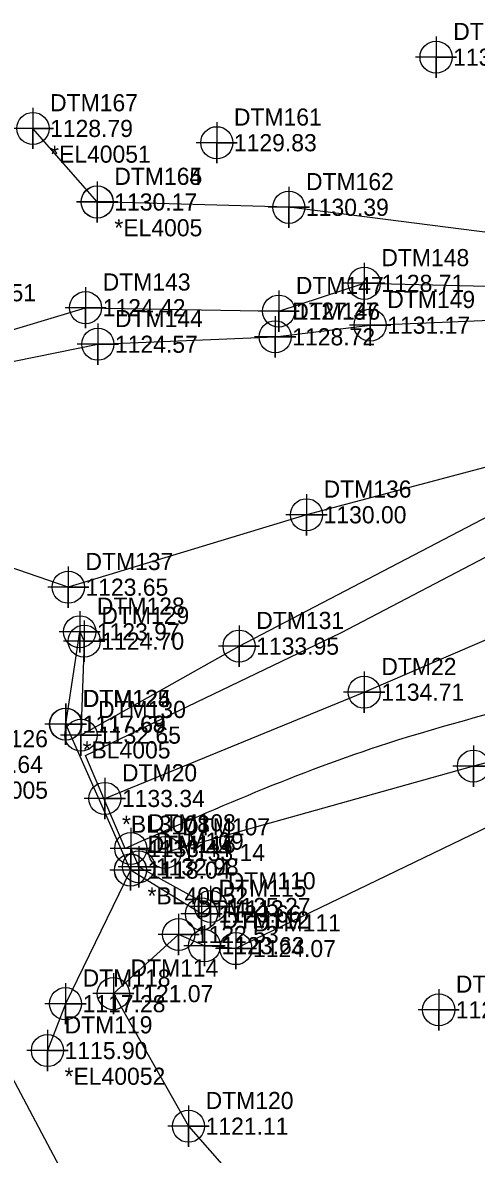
# Model space of a CAD drawing. Extents: x 1286409 to 1286829, y 857931 to 858308.
# Drawn here: x 1286649.1 to 1286715.3, y 858130 to 858295.1 of the extents above; entities that cross this region are included whole.
import ezdxf

# ---------------------------------------------------------------- set-up
doc = ezdxf.new("R2010")
doc.units = 0
for name, color, linetype in [('Exist DTM Breakline', 7, 'Continuous'), ('Exist DTM Breakline Cogo Comment', 7, 'Continuous'), ('Exist DTM Breakline Cogo Elevation', 7, 'Continuous'), ('Exist DTM Breakline Cogo Number', 7, 'Continuous'), ('Exist DTM Breakline Cogo Point CELL', 7, 'Continuous'), ('Exist DTM Crownline', 7, 'Continuous'), ('Exist DTM Crownline Cogo Comment', 7, 'Continuous'), ('Exist DTM Crownline Cogo Elevation', 7, 'Continuous'), ('Exist DTM Crownline Cogo Number', 7, 'Continuous'), ('Exist DTM Crownline Cogo Point CELL', 7, 'Continuous'), ('Exist DTM Regular Point CELL', 7, 'Continuous'), ('Exist DTM Regular Point Cogo Elevation', 7, 'Continuous'), ('Exist DTM Regular Point Cogo Number', 7, 'Continuous'), ('Exist Hydro Stream or Body of Water', 7, 'Continuous'), ('Exist Roads EOP', 7, 'Continuous')]:
    doc.layers.add(name, color=color, linetype=linetype)

msp = doc.modelspace()

# ---------------------------------------------------------------- linework, layer by layer
at = {"layer": 'Exist DTM Breakline'}
for points in [[(1286632.493, 858242.571), (1286660.074, 858248.148), (1286685.945, 858249.23), (1286699.802, 858250.923), (1286734.824, 858252.386), (1286736.062, 858257.139), (1286731.751, 858264.514), (1286727.165, 858263.134), (1286687.944, 858268.125), (1286659.976, 858268.899), (1286650.61, 858279.628)], [(1286616.952, 858240.566), (1286629.155, 858244.707), (1286658.287, 858253.478), (1286686.461, 858252.975), (1286698.943, 858257.032), (1286730.846, 858256.269)], [(1286748.85, 858195.515), (1286714.87, 858186.6), (1286669.883, 858173.996), (1286664.879, 858174.577), (1286666.033, 858171.901), (1286676.529, 858166.124), (1286675.191, 858165.032), (1286664.853, 858171.436), (1286655.406, 858192.72), (1286657.428, 858206.193), (1286658.087, 858204.832), (1286657.611, 858191.117), (1286680.683, 858204.103), (1286719.44, 858224.327), (1286731.354, 858234.119), (1286690.517, 858223.266), (1286655.768, 858212.7), (1286632.397, 858220.726)], [(1286787.57, 858150.977), (1286775.181, 858174.894), (1286765.217, 858193.137), (1286755.797, 858193.361), (1286718.64, 858178.527), (1286680.221, 858159.977), (1286675.641, 858160.401), (1286671.867, 858162.031), (1286662.339, 858153.405), (1286673.303, 858134.067), (1286682.298, 858123.811), (1286697.007, 858100.077), (1286709.742, 858055.54)], [(1286664.828, 858171.428), (1286655.358, 858151.939), (1286652.726, 858145.104)]]:
    msp.add_lwpolyline(points, dxfattribs=at)
at = {"layer": 'Exist DTM Breakline Cogo Point CELL'}
for points in [[(1286650.61, 858282.628), (1286650.61, 858276.628), (1286650.61, 858279.628), (1286653.61, 858279.628), (1286647.61, 858279.628)], [(1286659.976, 858271.899), (1286659.976, 858265.899), (1286659.976, 858268.899), (1286662.976, 858268.899), (1286656.976, 858268.899)], [(1286659.988, 858271.89), (1286659.988, 858265.89), (1286659.988, 858268.89), (1286662.988, 858268.89), (1286656.988, 858268.89)], [(1286687.944, 858271.125), (1286687.944, 858265.125), (1286687.944, 858268.125), (1286690.944, 858268.125), (1286684.944, 858268.125)], [(1286698.943, 858260.032), (1286698.943, 858254.032), (1286698.943, 858257.032), (1286701.943, 858257.032), (1286695.943, 858257.032)], [(1286658.287, 858256.478), (1286658.287, 858250.478), (1286658.287, 858253.478), (1286661.287, 858253.478), (1286655.287, 858253.478)], [(1286686.461, 858255.975), (1286686.461, 858249.975), (1286686.461, 858252.975), (1286689.461, 858252.975), (1286683.461, 858252.975)], [(1286699.802, 858253.923), (1286699.802, 858247.923), (1286699.802, 858250.923), (1286702.802, 858250.923), (1286696.802, 858250.923)], [(1286685.945, 858252.23), (1286685.945, 858246.23), (1286685.945, 858249.23), (1286688.945, 858249.23), (1286682.945, 858249.23)], [(1286660.074, 858251.148), (1286660.074, 858245.148), (1286660.074, 858248.148), (1286663.074, 858248.148), (1286657.074, 858248.148)], [(1286690.517, 858226.266), (1286690.517, 858220.266), (1286690.517, 858223.266), (1286693.517, 858223.266), (1286687.517, 858223.266)], [(1286655.768, 858215.7), (1286655.768, 858209.7), (1286655.768, 858212.7), (1286658.768, 858212.7), (1286652.768, 858212.7)], [(1286657.428, 858209.193), (1286657.428, 858203.193), (1286657.428, 858206.193), (1286660.428, 858206.193), (1286654.428, 858206.193)], [(1286658.087, 858207.832), (1286658.087, 858201.832), (1286658.087, 858204.832), (1286661.087, 858204.832), (1286655.087, 858204.832)], [(1286680.683, 858207.103), (1286680.683, 858201.103), (1286680.683, 858204.103), (1286683.683, 858204.103), (1286677.683, 858204.103)], [(1286655.354, 858195.717), (1286655.354, 858189.717), (1286655.354, 858192.717), (1286658.354, 858192.717), (1286652.354, 858192.717)], [(1286655.406, 858195.72), (1286655.406, 858189.72), (1286655.406, 858192.72), (1286658.406, 858192.72), (1286652.406, 858192.72)], [(1286657.611, 858194.117), (1286657.611, 858188.117), (1286657.611, 858191.117), (1286660.611, 858191.117), (1286654.611, 858191.117)], [(1286714.87, 858189.6), (1286714.87, 858183.6), (1286714.87, 858186.6), (1286717.87, 858186.6), (1286711.87, 858186.6)], [(1286664.879, 858177.577), (1286664.879, 858171.577), (1286664.879, 858174.577), (1286667.879, 858174.577), (1286661.879, 858174.577)], [(1286669.883, 858176.996), (1286669.883, 858170.996), (1286669.883, 858173.996), (1286672.883, 858173.996), (1286666.883, 858173.996)], [(1286664.828, 858174.428), (1286664.828, 858168.428), (1286664.828, 858171.428), (1286667.828, 858171.428), (1286661.828, 858171.428)], [(1286664.853, 858174.436), (1286664.853, 858168.436), (1286664.853, 858171.436), (1286667.853, 858171.436), (1286661.853, 858171.436)], [(1286666.033, 858174.901), (1286666.033, 858168.901), (1286666.033, 858171.901), (1286669.033, 858171.901), (1286663.033, 858171.901)], [(1286675.191, 858168.032), (1286675.191, 858162.032), (1286675.191, 858165.032), (1286678.191, 858165.032), (1286672.191, 858165.032)], [(1286676.529, 858169.124), (1286676.529, 858163.124), (1286676.529, 858166.124), (1286679.529, 858166.124), (1286673.529, 858166.124)], [(1286671.867, 858165.031), (1286671.867, 858159.031), (1286671.867, 858162.031), (1286674.867, 858162.031), (1286668.867, 858162.031)], [(1286675.641, 858163.401), (1286675.641, 858157.401), (1286675.641, 858160.401), (1286678.641, 858160.401), (1286672.641, 858160.401)], [(1286680.221, 858162.977), (1286680.221, 858156.977), (1286680.221, 858159.977), (1286683.221, 858159.977), (1286677.221, 858159.977)], [(1286662.339, 858156.405), (1286662.339, 858150.405), (1286662.339, 858153.405), (1286665.339, 858153.405), (1286659.339, 858153.405)], [(1286655.358, 858154.939), (1286655.358, 858148.939), (1286655.358, 858151.939), (1286658.358, 858151.939), (1286652.358, 858151.939)], [(1286652.726, 858148.104), (1286652.726, 858142.104), (1286652.726, 858145.104), (1286655.726, 858145.104), (1286649.726, 858145.104)], [(1286673.303, 858137.067), (1286673.303, 858131.067), (1286673.303, 858134.067), (1286676.303, 858134.067), (1286670.303, 858134.067)]]:
    msp.add_lwpolyline(points, dxfattribs=at)
for centre in [(1286650.61, 858279.628), (1286659.976, 858268.899), (1286659.988, 858268.89), (1286687.944, 858268.125), (1286698.943, 858257.032), (1286658.287, 858253.478), (1286686.461, 858252.975), (1286699.802, 858250.923), (1286660.074, 858248.148), (1286685.945, 858249.23), (1286690.517, 858223.266), (1286655.768, 858212.7), (1286657.428, 858206.193), (1286658.087, 858204.832), (1286680.683, 858204.103), (1286655.354, 858192.717), (1286655.406, 858192.72), (1286657.611, 858191.117), (1286714.87, 858186.6), (1286664.879, 858174.577), (1286669.883, 858173.996), (1286666.033, 858171.901), (1286664.828, 858171.428), (1286664.853, 858171.436), (1286676.529, 858166.124), (1286675.191, 858165.032), (1286671.867, 858162.031), (1286675.641, 858160.401), (1286680.221, 858159.977), (1286662.339, 858153.405), (1286655.358, 858151.939), (1286652.726, 858145.104), (1286673.303, 858134.067)]:
    msp.add_circle(centre, 2.344, dxfattribs=at)
at = {"layer": 'Exist DTM Crownline'}
msp.add_lwpolyline([(1286661.096, 858181.88), (1286698.94, 858197.382), (1286724.907, 858208.588), (1286744.568, 858217.621), (1286760.393, 858225.322)], dxfattribs=at)
at = {"layer": 'Exist DTM Crownline Cogo Point CELL'}
for points in [[(1286698.94, 858200.382), (1286698.94, 858194.382), (1286698.94, 858197.382), (1286701.94, 858197.382), (1286695.94, 858197.382)], [(1286661.096, 858184.88), (1286661.096, 858178.88), (1286661.096, 858181.88), (1286664.096, 858181.88), (1286658.096, 858181.88)]]:
    msp.add_lwpolyline(points, dxfattribs=at)
for centre in [(1286698.94, 858197.382), (1286661.096, 858181.88)]:
    msp.add_circle(centre, 2.344, dxfattribs=at)
at = {"layer": 'Exist DTM Regular Point CELL'}
for points in [[(1286709.422, 858293.025), (1286709.422, 858287.025), (1286709.422, 858290.025), (1286712.422, 858290.025), (1286706.422, 858290.025)], [(1286677.425, 858280.541), (1286677.425, 858274.541), (1286677.425, 858277.541), (1286680.425, 858277.541), (1286674.425, 858277.541)], [(1286709.806, 858154.046), (1286709.806, 858148.046), (1286709.806, 858151.046), (1286712.806, 858151.046), (1286706.806, 858151.046)]]:
    msp.add_lwpolyline(points, dxfattribs=at)
for centre in [(1286709.422, 858290.025), (1286677.425, 858277.541), (1286709.806, 858151.046)]:
    msp.add_circle(centre, 2.344, dxfattribs=at)
at = {"layer": 'Exist Hydro Stream or Body of Water'}
msp.add_lwpolyline([(1286685.865, 858065.012), (1286665.776, 858106.892), (1286641.007, 858153.512), (1286624.223, 858201.931), (1286608.049, 858245.959), (1286588.044, 858292.077)], dxfattribs=at)
at = {"layer": 'Exist Roads EOP'}
for points in [[(1286658.291, 858188.167), (1286695.619, 858206.081), (1286719.784, 858218.735)], [(1286664.079, 858174.593), (1286658.291, 858188.167)]]:
    msp.add_lwpolyline(points, dxfattribs=at)
msp.add_spline([(1286787.169, 858167.69), (1286776.787, 858189.619), (1286767.655, 858197.136), (1286752.603, 858202.097), (1286728.107, 858197.379), (1286702.359, 858189.909), (1286664.079, 858174.593)], degree=3, dxfattribs=at)

# ---------------------------------------------------------------- texts
at = {"layer": 'Exist DTM Breakline Cogo Comment'}
for s, p in [('*EL40051', (1286653.11, 858274.628)), ('*EL4005', (1286662.488, 858263.89)), ('*EL40051', (1286636.373, 858254.409)), ('*BL4005', (1286657.854, 858187.717)), ('*BL4005', (1286639.973, 858181.849)), ('*BL40052', (1286667.328, 858166.428)), ('*EL40052', (1286655.226, 858140.104))]:
    msp.add_text(s, height=2.5, dxfattribs=at).set_placement(p)
at = {"layer": 'Exist DTM Breakline Cogo Elevation'}
for s, p in [('1128.79', (1286653.11, 858278.378)), ('1130.17', (1286662.476, 858267.649)), ('1130.17', (1286662.488, 858267.64)), ('1130.39', (1286690.444, 858266.875)), ('1128.71', (1286701.443, 858255.782)), ('1124.42', (1286660.787, 858252.228)), ('1127.37', (1286688.961, 858251.725)), ('1131.17', (1286702.302, 858249.673)), ('1128.72', (1286688.445, 858247.98)), ('1124.57', (1286662.574, 858246.898)), ('1130.00', (1286693.017, 858222.016)), ('1123.65', (1286658.268, 858211.45)), ('1123.97', (1286659.928, 858204.943)), ('1124.70', (1286660.587, 858203.582)), ('1133.95', (1286683.183, 858202.853)), ('1117.68', (1286657.854, 858191.467)), ('1117.69', (1286657.906, 858191.47)), ('1132.65', (1286660.111, 858189.867)), ('1115.64', (1286639.973, 858185.599)), ('1133.44', (1286667.379, 858173.327)), ('1133.14', (1286672.383, 858172.746)), ('1118.04', (1286667.328, 858170.178)), ('1118.04', (1286667.353, 858170.186)), ('1132.98', (1286668.533, 858170.651)), ('1123.66', (1286677.691, 858163.782)), ('1125.27', (1286679.029, 858164.874)), ('1122.53', (1286674.367, 858160.781)), ('1123.63', (1286678.141, 858159.151)), ('1124.07', (1286682.721, 858158.727)), ('1121.07', (1286664.839, 858152.155)), ('1117.28', (1286657.858, 858150.689)), ('1115.90', (1286655.226, 858143.854)), ('1121.11', (1286675.803, 858132.817))]:
    msp.add_text(s, height=2.5, dxfattribs=at).set_placement(p)
at = {"layer": 'Exist DTM Breakline Cogo Number'}
for s, p in [('DTM167', (1286653.11, 858282.128)), ('DTM164', (1286662.476, 858271.399)), ('DTM165', (1286662.488, 858271.39)), ('DTM162', (1286690.444, 858270.625)), ('DTM148', (1286701.443, 858259.532)), ('DTM143', (1286660.787, 858255.978)), ('DTM147', (1286688.961, 858255.475)), ('DTM149', (1286702.302, 858253.423)), ('DTM146', (1286688.445, 858251.73)), ('DTM144', (1286662.574, 858250.648)), ('DTM136', (1286693.017, 858225.766)), ('DTM137', (1286658.268, 858215.2)), ('DTM128', (1286659.928, 858208.693)), ('DTM129', (1286660.587, 858207.332)), ('DTM131', (1286683.183, 858206.603)), ('DTM125', (1286657.854, 858195.217)), ('DTM124', (1286657.906, 858195.22)), ('DTM130', (1286660.111, 858193.617)), ('DTM126', (1286639.973, 858189.349)), ('DTM108', (1286667.379, 858177.077)), ('DTM107', (1286672.383, 858176.496)), ('DTM117', (1286667.328, 858173.928)), ('DTM116', (1286667.353, 858173.936)), ('DTM109', (1286668.533, 858174.401)), ('DTM110', (1286679.029, 858168.624)), ('DTM115', (1286677.691, 858167.532)), ('DTM113', (1286674.367, 858164.531)), ('DTM112', (1286678.141, 858162.901)), ('DTM111', (1286682.721, 858162.477)), ('DTM114', (1286664.839, 858155.905)), ('DTM118', (1286657.858, 858154.439)), ('DTM119', (1286655.226, 858147.604)), ('DTM120', (1286675.803, 858136.567))]:
    msp.add_text(s, height=2.5, dxfattribs=at).set_placement(p)
at = {"layer": 'Exist DTM Crownline Cogo Comment'}
msp.add_text('*BL3008', height=2.5, dxfattribs=at).set_placement((1286663.596, 858176.88))
at = {"layer": 'Exist DTM Crownline Cogo Elevation'}
for s, p in [('1134.71', (1286701.44, 858196.132)), ('1133.34', (1286663.596, 858180.63))]:
    msp.add_text(s, height=2.5, dxfattribs=at).set_placement(p)
at = {"layer": 'Exist DTM Crownline Cogo Number'}
for s, p in [('DTM22', (1286701.44, 858199.882)), ('DTM20', (1286663.596, 858184.38))]:
    msp.add_text(s, height=2.5, dxfattribs=at).set_placement(p)
at = {"layer": 'Exist DTM Regular Point Cogo Elevation'}
for s, p in [('1132.80', (1286711.922, 858288.775)), ('1129.83', (1286679.925, 858276.291)), ('1127.35', (1286712.306, 858149.796))]:
    msp.add_text(s, height=2.5, dxfattribs=at).set_placement(p)
at = {"layer": 'Exist DTM Regular Point Cogo Number'}
for s, p in [('DTM159', (1286711.922, 858292.525)), ('DTM161', (1286679.925, 858280.041)), ('DTM91', (1286712.306, 858153.546))]:
    msp.add_text(s, height=2.5, dxfattribs=at).set_placement(p)

doc.saveas('drawing.dxf')
